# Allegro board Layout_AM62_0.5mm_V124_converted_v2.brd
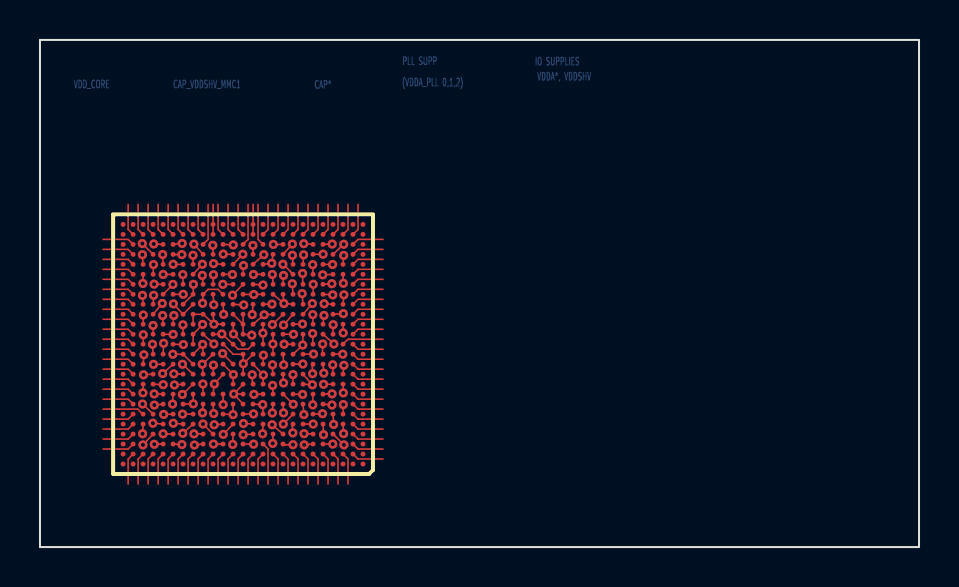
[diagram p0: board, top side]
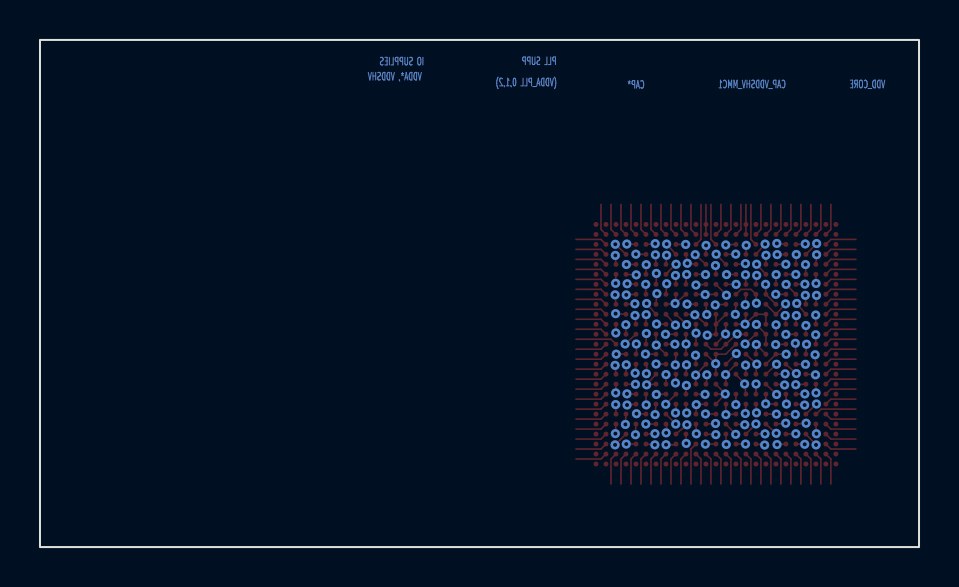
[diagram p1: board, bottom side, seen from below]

Outline 43.98 x 25.4 mm; copper layers: TOP, INNER LAYER 2, INNER LAYER 3, INNER LAYER 4, INNER LAYER 5, BOTTOM. Coordinates in mm from the lower left corner of the outline.
Outline path: rectangle 0,0 43.98,25.4

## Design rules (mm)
constraint set DEFAULT: min track width 0.081

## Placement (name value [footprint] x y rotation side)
U1  -  [AM62_20210511]  10.16 10.16 0 top

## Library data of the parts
U1 = AM62_20210511

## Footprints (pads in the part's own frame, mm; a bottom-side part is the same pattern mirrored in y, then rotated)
AM62_20210511
  round 0.249 smd: A1(6,-6) A2(5.5,-6) A3(5,-6) A4(4.5,-6) A5(4,-6) A6(3.5,-6) A7(3,-6) A8(2.5,-6) A9(2,-6) A10(1.5,-6) A11(1,-6) A12(0.5,-6) A13(0,-6) A14(-0.5,-6) A15(-1,-6) A16(-1.5,-6) A17(-2,-6) A18(-2.5,-6) A19(-3,-6) A20(-3.5,-6) A21(-4,-6) A22(-4.5,-6) A23(-5,-6) A24(-5.5,-6) A25(-6,-6) AA1(6,4) AA2(5.5,4) AA3(5,4) AA5(4,4) AA7(3,4) AA8(2.5,4) AA11(1,4) AA12(0.5,4) AA14(-0.5,4) AA15(-1,4) AA18(-2.5,4) AA19(-3,4) AA21(-4,4) AA23(-5,4) AA24(-5.5,4) AA25(-6,4) AB1(6,4.5) AB2(5.5,4.5) AB4(4.5,4.5) AB6(3.5,4.5) AB9(2,4.5) AB10(1.5,4.5) AB12(0.5,4.5) AB14(-0.5,4.5) AB16(-1.5,4.5) AB17(-2,4.5) AB20(-3.5,4.5) AB22(-4.5,4.5) AB24(-5.5,4.5) AB25(-6,4.5) AC1(6,5) AC2(5.5,5) AC5(4,5) AC6(3.5,5) AC9(2,5) AC11(1,5) AC13(0,5) AC15(-1,5) AC17(-2,5) AC20(-3.5,5) AC21(-4,5) AC24(-5.5,5) AC25(-6,5) AD1(6,5.5) AD2(5.5,5.5) AD3(5,5.5) AD4(4.5,5.5) AD5(4,5.5) AD6(3.5,5.5) AD7(3,5.5) AD8(2.5,5.5) AD9(2,5.5) AD10(1.5,5.5) AD11(1,5.5) AD12(0.5,5.5) AD13(0,5.5) AD14(-0.5,5.5) AD15(-1,5.5) AD16(-1.5,5.5) AD17(-2,5.5) AD18(-2.5,5.5) AD19(-3,5.5) AD20(-3.5,5.5) AD21(-4,5.5) AD22(-4.5,5.5) AD23(-5,5.5) AD24(-5.5,5.5) AD25(-6,5.5) AE1(6,6) AE2(5.5,6) AE3(5,6) AE4(4.5,6) AE5(4,6) AE6(3.5,6) AE7(3,6) AE8(2.5,6) AE9(2,6) AE10(1.5,6) AE11(1,6) AE12(0.5,6) AE13(0,6) AE14(-0.5,6) AE15(-1,6) AE16(-1.5,6) AE17(-2,6) AE18(-2.5,6) AE19(-3,6) AE20(-3.5,6) AE21(-4,6) AE22(-4.5,6) AE23(-5,6) AE24(-5.5,6) AE25(-6,6) B1(6,-5.5) B2(5.5,-5.5) B3(5,-5.5) B4(4.5,-5.5) B5(4,-5.5) B6(3.5,-5.5) B7(3,-5.5) B8(2.5,-5.5) B9(2,-5.5) B10(1.5,-5.5) B11(1,-5.5) B12(0.5,-5.5) B13(0,-5.5) B14(-0.5,-5.5) B15(-1,-5.5) B16(-1.5,-5.5) B17(-2,-5.5) B18(-2.5,-5.5) B19(-3,-5.5) B20(-3.5,-5.5) B21(-4,-5.5) B22(-4.5,-5.5) B23(-5,-5.5) B24(-5.5,-5.5) B25(-6,-5.5) C1(6,-5) C2(5.5,-5) C5(4,-5) C6(3.5,-5) C9(2,-5) C11(1,-5) C13(0,-5) C15(-1,-5) C17(-2,-5) C20(-3.5,-5) C21(-4,-5) C24(-5.5,-5) C25(-6,-5) D1(6,-4.5) D2(5.5,-4.5) D4(4.5,-4.5) D6(3.5,-4.5) D9(2,-4.5) D10(1.5,-4.5) D12(0.5,-4.5) D14(-0.5,-4.5) D16(-1.5,-4.5) D17(-2,-4.5) D20(-3.5,-4.5) D22(-4.5,-4.5) D24(-5.5,-4.5) D25(-6,-4.5) E1(6,-4) E2(5.5,-4) E3(5,-4) E5(4,-4) E7(3,-4) E8(2.5,-4) E11(1,-4) E12(0.5,-4) E14(-0.5,-4) E15(-1,-4) E18(-2.5,-4) E19(-3,-4) E21(-4,-4) E23(-5,-4) E24(-5.5,-4) E25(-6,-4) F1(6,-3.5) F2(5.5,-3.5) F3(5,-3.5) F4(4.5,-3.5) F6(3.5,-3.5) F8(2.5,-3.5) F11(1,-3.5) F13(0,-3.5) F15(-1,-3.5) F18(-2.5,-3.5) F20(-3.5,-3.5) F22(-4.5,-3.5) F23(-5,-3.5) F24(-5.5,-3.5) F25(-6,-3.5) G1(6,-3) G2(5.5,-3) G5(4,-3) G7(3,-3) G9(2,-3) G10(1.5,-3) G12(0.5,-3) G13(0,-3) G14(-0.5,-3) G16(-1.5,-3) G17(-2,-3) G19(-3,-3) G21(-4,-3) G24(-5.5,-3) G25(-6,-3) H1(6,-2.5) H2(5.5,-2.5) H5(4,-2.5) H6(3.5,-2.5) H8(2.5,-2.5) H9(2,-2.5) H10(1.5,-2.5) H11(1,-2.5) H13(0,-2.5) H15(-1,-2.5) H16(-1.5,-2.5) H17(-2,-2.5) H18(-2.5,-2.5) H20(-3.5,-2.5) H21(-4,-2.5) H24(-5.5,-2.5) H25(-6,-2.5) J1(6,-2) J2(5.5,-2) J3(5,-2) J4(4.5,-2) J7(3,-2) J8(2.5,-2) J11(1,-2) J12(0.5,-2) J13(0,-2) J14(-0.5,-2) J18(-2.5,-2) J19(-3,-2) J22(-4.5,-2) J23(-5,-2) J24(-5.5,-2) J25(-6,-2) K1(6,-1.5) K2(5.5,-1.5) K3(5,-1.5) K4(4.5,-1.5) K7(3,-1.5) K9(2,-1.5) K10(1.5,-1.5) K13(0,-1.5) K15(-1,-1.5) K16(-1.5,-1.5) K17(-2,-1.5) K18(-2.5,-1.5) K19(-3,-1.5) K22(-4.5,-1.5) K24(-5.5,-1.5) K25(-6,-1.5) L1(6,-1) L2(5.5,-1) L5(4,-1) L6(3.5,-1) L8(2.5,-1) L11(1,-1) L12(0.5,-1) L14(-0.5,-1) L15(-1,-1) L18(-2.5,-1) L20(-3.5,-1) L21(-4,-1) L23(-5,-1) L24(-5.5,-1) L25(-6,-1) M1(6,-0.5) M2(5.5,-0.5) M4(4.5,-0.5) M5(4,-0.5) M7(3,-0.5) M8(2.5,-0.5) M9(2,-0.5) M10(1.5,-0.5) M12(0.5,-0.5) M13(0,-0.5) M16(-1.5,-0.5) M17(-2,-0.5) M18(-2.5,-0.5) M19(-3,-0.5) M21(-4,-0.5) M22(-4.5,-0.5) M24(-5.5,-0.5) M25(-6,-0.5) N1(6,0) N2(5.5,0) N3(5,0) N6(3.5,0) N8(2.5,0) N11(1,0) N12(0.5,0) N13(0,0) N14(-0.5,0) N15(-1,0) N18(-2.5,0) N20(-3.5,0) N23(-5,0) N24(-5.5,0) N25(-6,0) P1(6,0.5) P2(5.5,0.5) P4(4.5,0.5) P5(4,0.5) P7(3,0.5) P9(2,0.5) P10(1.5,0.5) P13(0,0.5) P16(-1.5,0.5) P17(-2,0.5) P18(-2.5,0.5) P19(-3,0.5) P21(-4,0.5) P22(-4.5,0.5) P24(-5.5,0.5) P25(-6,0.5) R1(6,1) R2(5.5,1) R3(5,1) R5(4,1) R6(3.5,1) R8(2.5,1) R11(1,1) R12(0.5,1) R13(0,1) R14(-0.5,1) R15(-1,1) R18(-2.5,1) R20(-3.5,1) R21(-4,1) R23(-5,1) R24(-5.5,1) R25(-6,1) T1(6,1.5) T2(5.5,1.5) T4(4.5,1.5) T7(3,1.5) T8(2.5,1.5) T9(2,1.5) T10(1.5,1.5) T13(0,1.5) T14(-0.5,1.5) T16(-1.5,1.5) T17(-2,1.5) T18(-2.5,1.5) T19(-3,1.5) T22(-4.5,1.5) T24(-5.5,1.5) T25(-6,1.5) U1(6,2) U2(5.5,2) U3(5,2) U4(4.5,2) U7(3,2) U8(2.5,2) U11(1,2) U12(0.5,2) U14(-0.5,2) U15(-1,2) U18(-2.5,2) U19(-3,2) U22(-4.5,2) U23(-5,2) U24(-5.5,2) U25(-6,2) V1(6,2.5) V2(5.5,2.5) V5(4,2.5) V6(3.5,2.5) V8(2.5,2.5) V9(2,2.5) V10(1.5,2.5) V11(1,2.5) V13(0,2.5) V15(-1,2.5) V16(-1.5,2.5) V17(-2,2.5) V18(-2.5,2.5) V20(-3.5,2.5) V21(-4,2.5) V24(-5.5,2.5) V25(-6,2.5) W1(6,3) W2(5.5,3) W5(4,3) W7(3,3) W9(2,3) W10(1.5,3) W12(0.5,3) W13(0,3) W14(-0.5,3) W16(-1.5,3) W17(-2,3) W19(-3,3) W21(-4,3) W24(-5.5,3) W25(-6,3) Y1(6,3.5) Y2(5.5,3.5) Y3(5,3.5) Y4(4.5,3.5) Y6(3.5,3.5) Y8(2.5,3.5) Y11(1,3.5) Y13(0,3.5) Y15(-1,3.5) Y18(-2.5,3.5) Y20(-3.5,3.5) Y22(-4.5,3.5) Y23(-5,3.5) Y24(-5.5,3.5) Y25(-6,3.5)

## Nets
VDD_CANUART: U1.F8
VDD_CORE: U1.H8 U1.J11 U1.J14 U1.K17 U1.L12 U1.L15 U1.M16 U1.N8 U1.N11 U1.N13 U1.P17 U1.R11 U1.R14 U1.U12 U1.V8 U1.V15 U1.V17
VDDA_1P8_CSIRX: U1.W14
VDDA_1P8_OLDI-0: U1.W9
VDDA_1P8_OLDI-1: U1.W10
VDDA_1P8_USB: U1.Y11
VDDA_3P3_USB: U1.Y13
VDDA_CORE_CSIRX: U1.W13
VDDA_CORE_USB: U1.W12
VDDA_MCU: U1.L11
VDDA_PLL0: U1.U11
VDDA_PLL1: U1.U15
VDDA_PLL2: U1.L14
VDDA_TEMP0: U1.T9
VDDA_TEMP1: U1.G16
VDDR_CORE: U1.J12 U1.K16 U1.N12 U1.N14 U1.P16 U1.R12 U1.T10 U1.U14
VDDS_DDR-0: U1.K9
VDDS_DDR-1: U1.L8
VDDS_DDR-2: U1.P9
VDDS_DDR-3: U1.R8
VDDS_DDR_C: U1.M9
VDDS_OSC: U1.G7
VDDSHV0: U1.F15 U1.G14
VDDSHV1: U1.L18 U1.M19
VDDSHV2: U1.W16 U1.W19
VDDSHV3: U1.N18 U1.P18 U1.T19 U1.U18
VDDSHV4: U1.T7
VDDSHV5: U1.G17
VDDSHV6: U1.J18
VDDSHV_CANUART: U1.H9
VDDSHV_MCU: U1.F11 U1.G12
VSS: U1.A1 U1.A24 U1.A25 U1.AA11 U1.AB10 U1.AD1 U1.AD12 U1.AD16 U1.AD25 U1.AE1 U1.AE12 U1.AE16 U1.AE24 U1.AE25 U1.B25 U1.F13 U1.G13 U1.G19 U1.H13 U1.H16 U1.H18 U1.J7 U1.J13 U1.K7 U1.K13 U1.K15 U1.K19 U1.M7 U1.M8 U1.M10 U1.M12 U1.M13 U1.M17 U1.M18 U1.N15 U1.P7 U1.P10 U1.P13 U1.R13 U1.R15 U1.R18 U1.T8 U1.T13 U1.T14 U1.T16 U1.T17 U1.T18 U1.U8 U1.U19 U1.V9 U1.V10 U1.V11 U1.V13 U1.V16 U1.V18 U1.W7
ATEST0: U1.F6
ATEST1: U1.AE2
CAP_VDDS0: U1.H15
CAP_VDDS1: U1.K18
CAP_VDDS2: U1.W17
CAP_VDDS3: U1.P19
CAP_VDDS4: U1.U7
CAP_VDDS5: U1.H17
CAP_VDDS6: U1.J19
CAP_VDDS_CANUART: U1.G9
CAP_VDDS_MCU: U1.H11
CSI0_ATB_0_H: U1.AA12
CSI0_ATB_1_H: U1.Y15
CSI0_RXCLKN: U1.AD15
CSI0_RXCLKP: U1.AE15
CSI0_RXN0: U1.AB14
CSI0_RXN1: U1.AD14
CSI0_RXN2: U1.AD13
CSI0_RXN3: U1.AB12
CSI0_RXP0: U1.AC15
CSI0_RXP1: U1.AE14
CSI0_RXP2: U1.AE13
CSI0_RXP3: U1.AC13
CSI0_RXRCALIB: U1.AA14
DDR0_A0: U1.J1
DDR0_A1: U1.J2
DDR0_A2: U1.K3
DDR0_A3: U1.L5
DDR0_A4: U1.K4
DDR0_A5: U1.K1
DDR0_A6: U1.R2
DDR0_A7: U1.P2
DDR0_A8: U1.P1
DDR0_A9: U1.P4
DDR0_A10: U1.R5
DDR0_A11: U1.P5
DDR0_A12: U1.R6
DDR0_A13: U1.R1
DDR0_ACT_N: U1.N6
DDR0_ALERT_N: U1.R3
DDR0_ATB0: U1.T2
DDR0_ATB1: U1.U4
DDR0_BA0: U1.M1
DDR0_BA1: U1.N1
DDR0_BG0: U1.T4
DDR0_BG1: U1.N2
DDR0_CAL0: U1.M2
DDR0_CAS_N: U1.M4
DDR0_CK0: U1.L1
DDR0_CK0_N: U1.L2
DDR0_CKE0: U1.H2
DDR0_CKE1: U1.J4
DDR0_CS0_N: U1.L6
DDR0_CS1_N: U1.K2
DDR0_DM0: U1.H5
DDR0_DM1: U1.W5
DDR0_DQ0: U1.F4
DDR0_DQ1: U1.G5
DDR0_DQ2: U1.F3
DDR0_DQ3: U1.H6
DDR0_DQ4: U1.E3
DDR0_DQ5: U1.G2
DDR0_DQ6: U1.F2
DDR0_DQ7: U1.F1
DDR0_DQ8: U1.U1
DDR0_DQ9: U1.U3
DDR0_DQ10: U1.U2
DDR0_DQ11: U1.V5
DDR0_DQ12: U1.W2
DDR0_DQ13: U1.V6
DDR0_DQ14: U1.Y1
DDR0_DQ15: U1.W1
DDR0_DQS0: U1.E1
DDR0_DQS0_N: U1.E2
DDR0_DQS1: U1.V1
DDR0_DQS1_N: U1.V2
DDR0_ODT0: U1.H1
DDR0_ODT1: U1.J3
DDR0_PAR: U1.T1
DDR0_RAS_N: U1.M5
DDR0_RESET0_N: U1.G1
DDR0_WE_N: U1.N3
EMU0: U1.E12
EMU1: U1.A10
EXT_REFCLK1: U1.D16
EXTINTN: U1.A18
GPMC0_AD0: U1.M25
GPMC0_AD1: U1.N23
GPMC0_AD2: U1.N24
GPMC0_AD3: U1.N25
GPMC0_AD4: U1.P24
GPMC0_AD5: U1.P22
GPMC0_AD6: U1.P21
GPMC0_AD7: U1.R24
GPMC0_AD8: U1.R25
GPMC0_AD9: U1.T25
GPMC0_AD10: U1.T24
GPMC0_AD11: U1.R21
GPMC0_AD12: U1.R20
GPMC0_AD13: U1.T22
GPMC0_AD14: U1.U25
GPMC0_AD15: U1.U24
GPMC0_ADVN_ALE: U1.L23
GPMC0_BE0N_CLE: U1.N20
GPMC0_BE1N: U1.M24
GPMC0_CLK: U1.R23
GPMC0_CLKLB: U1.P25
GPMC0_CSN0: U1.M21
GPMC0_CSN1: U1.L20
GPMC0_CSN2: U1.L21
GPMC0_CSN3: U1.K22
GPMC0_DIR: U1.M22
GPMC0_OEN_REN: U1.L24
GPMC0_WAIT0: U1.U23
GPMC0_WAIT1: U1.V25
GPMC0_WEN: U1.L25
GPMC0_WPN: U1.K25
I2C0_SCL: U1.B16
I2C0_SDA: U1.A16
I2C1_SCL: U1.B17
I2C1_SDA: U1.A17
IFORCE: U1.B1
MCAN0_RX: U1.E15
MCAN0_TX: U1.C15
MCASP0_ACLKR: U1.D20
MCASP0_ACLKX: U1.B20
MCASP0_AFSR: U1.E19
MCASP0_AFSX: U1.A20
MCASP0_AXR0: U1.E18
MCASP0_AXR1: U1.B18
MCASP0_AXR2: U1.A19
MCASP0_AXR3: U1.B19
MCU_ERRORN: U1.C2
MCU_I2C0_SCL: U1.A8
MCU_I2C0_SDA: U1.D10
MCU_MCAN0_RX: U1.B3
MCU_MCAN0_TX: U1.D6
MCU_MCAN1_RX: U1.D4
MCU_MCAN1_TX: U1.E5
MCU_OSC0_XI: U1.B2
MCU_OSC0_XO: U1.A3
MCU_PORZ: U1.D2
MCU_RESETSTATZ: U1.B12
MCU_RESETZ: U1.E11
MCU_SPI0_CLK: U1.E8
MCU_SPI0_CS0: U1.A7
MCU_SPI0_CS1: U1.B8
MCU_SPI0_D0: U1.D9
MCU_SPI0_D1: U1.C9
MCU_UART0_CTSN: U1.A6
MCU_UART0_RTSN: U1.B6
MCU_UART0_RXD: U1.B5
MCU_UART0_TXD: U1.A5
MDIO0_MDC: U1.AD24
MDIO0_MDIO: U1.AB22
MMC0_CLK: U1.Y4
MMC0_CLKLB: U1.AA3
MMC0_CMD: U1.Y3
MMC0_DAT0: U1.AA1
MMC0_DAT1: U1.Y2
MMC0_DAT2: U1.AA2
MMC0_DAT3: U1.AB1
MMC0_DAT4: U1.AB2
MMC0_DAT5: U1.AC1
MMC0_DAT6: U1.AD2
MMC0_DAT7: U1.AC2
MMC1_CLK: U1.B22
MMC1_CLKLB: U1.C21
MMC1_CMD: U1.A21
MMC1_DAT0: U1.A22
MMC1_DAT1: U1.B21
MMC1_DAT2: U1.D22
MMC1_DAT3: U1.E23
MMC1_SDCD: U1.D17
MMC1_SDWP: U1.C17
MMC2_CLK: U1.D25
MMC2_CLKLB: U1.D24
MMC2_CMD: U1.C24
MMC2_DAT0: U1.B24
MMC2_DAT1: U1.C25
MMC2_DAT2: U1.E24
MMC2_DAT3: U1.E25
MMC2_SDCD: U1.A23
MMC2_SDWP: U1.B23
OLDI0_A0N: U1.AA5
OLDI0_A0P: U1.Y6
OLDI0_A1N: U1.AD3
OLDI0_A1P: U1.AB4
OLDI0_A2N: U1.Y8
OLDI0_A2P: U1.AA8
OLDI0_A3N: U1.AB6
OLDI0_A3P: U1.AA7
OLDI0_A4N: U1.AC6
OLDI0_A4P: U1.AC5
OLDI0_A5N: U1.AE5
OLDI0_A5P: U1.AD6
OLDI0_A6N: U1.AE6
OLDI0_A6P: U1.AD7
OLDI0_A7N: U1.AD8
OLDI0_A7P: U1.AE7
OLDI0_CLK0N: U1.AD4
OLDI0_CLK0P: U1.AE3
OLDI0_CLK1N: U1.AE4
OLDI0_CLK1P: U1.AD5
OSPI0_CLK: U1.H24
OSPI0_CSN0: U1.F24
OSPI0_CSN1: U1.H20
OSPI0_CSN2: U1.G21
OSPI0_CSN3: U1.H21
OSPI0_D0: U1.F23
OSPI0_D1: U1.G25
OSPI0_D2: U1.G24
OSPI0_D3: U1.F25
OSPI0_D4: U1.J23
OSPI0_D5: U1.J25
OSPI0_D6: U1.H25
OSPI0_D7: U1.K24
OSPI0_DQS: U1.J24
OSPI0_LBCLKO: U1.J22
PMIC_LPM_EN0: U1.B7
PORZ_OUT: U1.E21
RESET_REQZ: U1.F20
RESETSTATZ: U1.F22
RGMII1_RD0: U1.AB17
RGMII1_RD1: U1.AC17
RGMII1_RD2: U1.AB16
RGMII1_RD3: U1.AA15
RGMII1_RX_CTL: U1.AE17
RGMII1_RXC: U1.AD17
RGMII1_TD0: U1.AE20
RGMII1_TD1: U1.AD20
RGMII1_TD2: U1.AE18
RGMII1_TD3: U1.AD18
RGMII1_TX_CTL: U1.AD19
RGMII1_TXC: U1.AE19
RGMII2_RD0: U1.AE23
RGMII2_RD1: U1.AB20
RGMII2_RD2: U1.AC21
RGMII2_RD3: U1.AE22
RGMII2_RX_CTL: U1.AD22
RGMII2_RXC: U1.AD23
RGMII2_TD0: U1.Y18
RGMII2_TD1: U1.AA18
RGMII2_TD2: U1.AD21
RGMII2_TD3: U1.AC20
RGMII2_TX_CTL: U1.AA19
RGMII2_TXC: U1.AE21
SPI0_CLK: U1.A14
SPI0_CS0: U1.A13
SPI0_CS1: U1.C13
SPI0_D0: U1.B13
SPI0_D1: U1.B14
TCK: U1.C11
TDI: U1.A11
TDO: U1.D12
TEMP_DIODE_P: U1.E7
TMS: U1.B11
TRSTN: U1.B10
UART0_CTSN: U1.A15
UART0_RTSN: U1.B15
UART0_RXD: U1.D14
UART0_TXD: U1.E14
USB0_DM: U1.AE11
USB0_DP: U1.AD11
USB0_DRVVBUS: U1.C20
USB0_ID: U1.AE10
USB0_RCALIB: U1.AD10
USB0_VBUS: U1.AC11
USB1_DM: U1.AD9
USB1_DP: U1.AE9
USB1_DRVVBUS: U1.F18
USB1_ID: U1.AC9
USB1_RCALIB: U1.AB9
USB1_VBUS: U1.AE8
VMON_1P8_SOC: U1.G10
VMON_3P3_SOC: U1.K10
VMON_VSYS: U1.H10
VOUT0_DATA0: U1.U22
VOUT0_DATA1: U1.V24
VOUT0_DATA2: U1.W25
VOUT0_DATA3: U1.W24
VOUT0_DATA4: U1.Y25
VOUT0_DATA5: U1.Y24
VOUT0_DATA6: U1.Y23
VOUT0_DATA7: U1.AA25
VOUT0_DATA8: U1.V21
VOUT0_DATA9: U1.W21
VOUT0_DATA10: U1.V20
VOUT0_DATA11: U1.AA23
VOUT0_DATA12: U1.AB25
VOUT0_DATA13: U1.AA24
VOUT0_DATA14: U1.Y22
VOUT0_DATA15: U1.AB24
VOUT0_DE: U1.AA21
VOUT0_HSYNC: U1.AC25
VOUT0_PCLK: U1.Y20
VOUT0_VSYNC: U1.AC24
VPP: U1.J8
VSENSE: U1.A2
WKUP_CLKOUT0: U1.A12
WKUP_I2C0_SCL: U1.B9
WKUP_I2C0_SDA: U1.A9
WKUP_LFOSC0_XI: U1.C1
WKUP_LFOSC0_XO: U1.D1
WKUP_UART0_CTSN: U1.C6
WKUP_UART0_RTSN: U1.A4
WKUP_UART0_RXD: U1.B4
WKUP_UART0_TXD: U1.C5

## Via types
v1: diameter 0.457, hole 0.203, TOP to BOTTOM, 198 vias

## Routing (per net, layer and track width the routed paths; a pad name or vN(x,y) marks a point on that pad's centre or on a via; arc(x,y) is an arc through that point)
VDD_CANUART: length 0.7
  TOP w0.081: v1(12.17,6.16) U1.F8
VDD_CORE: length 10.2
  TOP w0.081: U1.M16 v1(8.12,9.16) U1.K17 ; U1.P17 v1(8.7,10.17) ; U1.R11 v1(11.16,10.71) U1.N11 ; v1(8.14,12.21) U1.V17 8.41,12.91 8.91,12.91 9.16,12.66 U1.V15 ; U1.J11 v1(11.17,8.61) U1.L12 ; U1.R14 v1(9.68,10.67) U1.N13 ; U1.L15 v1(9.68,8.64) U1.J14 ; v1(12.21,10.16) U1.N8 ; U1.H8 v1(13.14,7.64) ; v1(12.62,13.19) U1.V8 ; v1(10.62,11.65) U1.U12
VDDA_1P8_CSIRX: length 0.5
  TOP w0.081: v1(9.15,13.16) U1.W14
VDDA_1P8_OLDI-0: length 0.4
  TOP w0.081: U1.W9 v1(12.18,13.6)
VDDA_1P8_OLDI-1: length 0.5
  TOP w0.081: U1.W10 11.66,13.28 v1(11.62,13.65)
VDDA_1P8_USB: length 0.5
  TOP w0.081: v1(10.68,13.65) 10.69,13.66 U1.Y11
VDDA_3P3_USB: length 0.4
  TOP w0.081: U1.Y13 v1(10.18,14.1)
VDDA_CORE_CSIRX: length 0.8
  TOP w0.081: v1(9.63,12.61) U1.W13
VDDA_CORE_USB: length 0.5
  TOP w0.081: U1.W12 v1(11.16,13.13)
VDDA_MCU: length 0.5
  TOP w0.081: U1.L11 v1(11.18,9.61)
VDDA_PLL0: length 0.4
  TOP w0.081: U1.U11 v1(11.61,12.17)
VDDA_PLL1: length 0.5
  TOP w0.081: U1.U15 v1(9.19,11.66)
VDDA_PLL2: length 0.7
  TOP w0.081: v1(9.14,9.69) U1.L14
VDDA_TEMP0: length 0.7
  TOP w0.081: v1(11.63,11.15) U1.T9
VDDA_TEMP1: length 0.5
  TOP w0.081: U1.G16 v1(8.69,6.69)
VDDR_CORE: length 5.1
  TOP w0.081: U1.R12 v1(11.21,11.63) U1.T10 ; U1.P16 9.1,10.64 v1(9.1,10.67) 9.15,10.64 U1.N14 9.91,9.91 10.41,9.91 U1.N12 ; U1.U14 v1(10.19,12.13) ; U1.J12 10.63,8.28 v1(10.62,8.63) ; U1.K16 v1(8.68,9.11)
VDDS_DDR-0: length 0.4
  TOP w0.081: U1.K9 v1(12.19,8.22)
VDDS_DDR-1: length 0.5
  TOP w0.081: U1.L8 v1(13.15,9.17)
VDDS_DDR-2: length 0.5
  TOP w0.081: U1.P9 v1(12.68,10.66)
VDDS_DDR-3: length 0.5
  TOP w0.081: U1.R8 v1(13.13,11.17)
VDDS_DDR_C: length 0.5
  TOP w0.081: U1.M9 v1(12.19,9.12)
VDDS_OSC: length 0.5
  TOP w0.081: U1.G7 v1(13.2,6.63)
VDDSHV0: length 1
  TOP w0.081: U1.G14 v1(9.66,6.63) U1.F15
VDDSHV1: length 1.2
  TOP w0.081: U1.L18 U1.M19 v1(6.65,9.66)
VDDSHV2: length 1
  TOP w0.081: v1(7.15,13.65) U1.W19 ; U1.W16 v1(8.68,13.64)
VDDSHV3: length 2.6
  TOP w0.081: v1(6.68,12.18) U1.T19 U1.U18 ; v1(8.14,11.15) U1.P18 U1.N18
VDDSHV4: length 0.7
  TOP w0.081: U1.T7 v1(13.63,12.2)
VDDSHV5: length 0.4
  TOP w0.081: v1(8.13,6.72) U1.G17
VDDSHV6: length 0.7
  TOP w0.081: v1(7.12,7.64) U1.J18
VDDSHV_CANUART: length 0.7
  TOP w0.081: U1.H9 v1(12.67,7.15)
VDDSHV_MCU: length 1
  TOP w0.081: U1.G12 v1(11.14,7.13) U1.F11
VSS: length 27.3
  TOP w0.081: v1(10.17,9.18) U1.M13 9.67,9.66 9.16,10.16 U1.N15 ; v1(10.17,9.18) U1.K13 ; v1(10.17,9.18) U1.M12 ; U1.K7 v1(13.63,8.13) U1.J7 ; U1.AA11 v1(11.59,14.21) U1.AB10 ; U1.U19 7.16,12.16 7.66,12.66 U1.V18 v1(7.68,13.16) ; U1.P10 v1(11.65,10.17) U1.M10 ; U1.T14 U1.R13 ; U1.R13 U1.T13 ; U1.R13 U1.P13 v1(10.6,10.61) ; U1.W7 13.15,13.16 v1(13.14,13.71) ; U1.H18 v1(7.67,7.17) U1.G19 ; U1.K15 v1(8.72,8.17) U1.H16 ; U1.M8 v1(13.15,10.12) U1.P7 ; U1.V9 v1(12.2,12.2) ; v1(12.2,12.2) U1.V10 ; v1(12.2,12.2) U1.U8 ; v1(8.7,11.16) U1.R15 ; v1(8.7,11.16) U1.T16 ; v1(8.7,11.16) U1.T17 U1.T18 U1.R18 ; U1.AD12 U1.AE12 10.66,17.16 ; U1.M18 v1(8.14,10.15) U1.M17 ; U1.H13 v1(9.69,7.67) ; v1(9.69,7.67) U1.J13 ; v1(9.69,7.67) U1.G13 ; U1.M7 v1(13.69,9.67) ; U1.F13 v1(10.68,6.67) ; U1.V11 v1(10.7,12.65) U1.V13 ; v1(12.18,11.12) U1.T8 ; U1.V16 v1(8.69,12.14) ; v1(6.7,8.68) U1.K19 ; 8.66,17.16 U1.AE16 U1.AD16
ATEST0: length 0.5
  TOP w0.081: U1.F6 v1(14.14,6.68)
CAP_VDDS0: length 0.5
  TOP w0.081: U1.H15 v1(9.16,7.14)
CAP_VDDS1: length 0.7
  TOP w0.081: v1(7.13,9.16) U1.K18
CAP_VDDS2: length 0.4
  TOP w0.081: v1(8.12,13.61) U1.W17
CAP_VDDS3: length 0.5
  TOP w0.081: v1(7.15,11.13) U1.P19
CAP_VDDS4: length 0.5
  TOP w0.081: v1(13.11,12.69) U1.U7
CAP_VDDS5: length 0.5
  TOP w0.081: v1(8.15,8.17) U1.H17
CAP_VDDS6: length 0.4
  TOP w0.081: v1(6.72,8.12) U1.J19
CAP_VDDS_CANUART: length 0.4
  TOP w0.081: U1.G9 v1(12.18,6.72)
CAP_VDDS_MCU: length 0.5
  TOP w0.081: v1(10.7,7.65) U1.H11
CSI0_ATB_0_H: length 0.7
  TOP w0.081: U1.AA12 v1(11.2,14.64)
CSI0_ATB_1_H: length 0.5
  TOP w0.081: U1.Y15 v1(9.63,13.65)
CSI0_RXCLKN: length 1.6
  TOP w0.081: 8.91,17.16 8.91,15.91 U1.AD15
CSI0_RXN0: length 0.5
  TOP w0.081: v1(9.17,14.67) U1.AB14
CSI0_RXN1: length 1.6
  TOP w0.081: U1.AD14 9.41,15.91 9.41,17.16
CSI0_RXN2: length 1.6
  TOP w0.081: U1.AD13 9.91,15.91 9.91,17.16
CSI0_RXN3: length 0.4
  TOP w0.081: v1(10.65,15.11) U1.AB12
CSI0_RXP0: length 0.5
  TOP w0.081: U1.AC15 v1(9.67,15.13)
CSI0_RXP3: length 2.1
  TOP w0.081: 10.41,17.16 10.41,15.41 U1.AC13
CSI0_RXRCALIB: length 0.7
  TOP w0.081: U1.AA14 v1(10.15,14.67)
DDR0_A1: length 1.6
  TOP w0.081: 17.16,7.91 15.91,7.91 U1.J2
DDR0_A2: length 0.4
  TOP w0.081: U1.K3 v1(15.2,9.1)
DDR0_A3: length 0.5
  TOP w0.081: U1.L5 v1(14.2,8.71)
DDR0_A4: length 0.5
  TOP w0.081: v1(14.65,9.13) U1.K4
DDR0_A6: length 1.6
  TOP w0.081: 17.16,11.41 15.91,11.41 U1.R2
DDR0_A7: length 1.6
  TOP w0.081: 17.16,10.91 15.91,10.91 U1.P2
DDR0_A9: length 0.5
  TOP w0.081: U1.P4 v1(14.67,11.14)
DDR0_A10: length 0.4
  TOP w0.081: U1.R5 v1(14.21,11.6)
DDR0_A11: length 0.7
  TOP w0.081: U1.P5 v1(14.7,10.17)
DDR0_A12: length 0.5
  TOP w0.081: v1(13.65,11.64) U1.R6
DDR0_ACT_N: length 0.5
  TOP w0.081: v1(13.64,10.7) U1.N6
DDR0_ALERT_N: length 0.4
  TOP w0.081: U1.R3 v1(15.17,10.72)
DDR0_ATB0: length 1.6
  TOP w0.081: U1.T2 15.91,11.91 17.16,11.91
DDR0_ATB1: length 0.4
  TOP w0.081: v1(14.21,12.19) U1.U4
DDR0_BG0: length 0.5
  TOP w0.081: U1.T4 v1(15.18,11.69)
DDR0_BG1: length 1.6
  TOP w0.081: U1.N2 15.91,9.91 17.16,9.91
DDR0_CAL0: length 1.6
  TOP w0.081: 17.16,9.41 15.91,9.41 U1.M2
DDR0_CAS_N: length 0.5
  TOP w0.081: U1.M4 14.66,9.67 v1(15.15,9.66)
DDR0_CK0_N: length 1.6
  TOP w0.081: U1.L2 15.91,8.91 17.16,8.91
DDR0_CKE0: length 1.6
  TOP w0.081: 17.16,7.41 15.91,7.41 U1.H2
DDR0_CKE1: length 0.5
  TOP w0.081: v1(14.19,8.15) U1.J4
DDR0_CS0_N: length 0.5
  TOP w0.081: U1.L6 13.61,9.16 v1(13.64,8.69)
DDR0_CS1_N: length 1.6
  TOP w0.081: U1.K2 15.91,8.41 17.16,8.41
DDR0_DM0: length 0.5
  TOP w0.081: U1.H5 v1(14.61,7.67)
DDR0_DM1: length 0.4
  TOP w0.081: U1.W5 v1(14.6,13.19)
DDR0_DQ0: length 0.5
  TOP w0.081: U1.F4 v1(14.69,6.14)
DDR0_DQ1: length 0.4
  TOP w0.081: U1.G5 v1(14.61,7.12)
DDR0_DQ2: length 0.5
  TOP w0.081: U1.F3 v1(15.17,7.14)
DDR0_DQ3: length 0.5
  TOP w0.081: v1(13.65,7.12) U1.H6
DDR0_DQ4: length 0.5
  TOP w0.081: U1.E3 v1(15.19,5.68)
DDR0_DQ5: length 1.6
  TOP w0.081: U1.G2 15.91,6.91 17.16,6.91
DDR0_DQ6: length 1.6
  TOP w0.081: 17.16,6.41 15.91,6.41 U1.F2
DDR0_DQ9: length 0.5
  TOP w0.081: U1.U3 v1(15.2,12.63)
DDR0_DQ10: length 1.6
  TOP w0.081: U1.U2 15.91,12.41 17.16,12.41
DDR0_DQ11: length 0.5
  TOP w0.081: U1.V5 v1(14.65,12.63)
DDR0_DQ12: length 1.6
  TOP w0.081: U1.W2 15.91,13.41 17.16,13.41
DDR0_DQ13: length 0.5
  TOP w0.081: U1.V6 v1(13.67,13.16)
DDR0_DQS0_N: length 1.6
  TOP w0.081: U1.E2 15.91,5.91 17.16,5.91
DDR0_DQS1_N: length 1.6
  TOP w0.081: 17.16,12.91 15.91,12.91 U1.V2
DDR0_ODT1: length 0.4
  TOP w0.081: U1.J3 v1(15.17,7.72)
DDR0_RAS_N: length 0.5
  TOP w0.081: U1.M5 14.13,9.66 v1(14.14,10.17)
DDR0_WE_N: length 2.1
  TOP w0.081: U1.N3 15.41,10.41 17.16,10.41
EMU0: length 0.5
  TOP w0.081: v1(10.18,6.19) U1.E12
EXT_REFCLK1: length 0.7
  TOP w0.081: v1(8.16,6.16) U1.D16
GPMC0_AD1: length 0.5
  TOP w0.081: U1.N23 v1(5.17,10.63)
GPMC0_AD2: length 1.6
  TOP w0.081: U1.N24 4.41,10.41 3.16,10.41
GPMC0_AD4: length 1.6
  TOP w0.081: U1.P24 4.41,10.91 3.16,10.91
GPMC0_AD5: length 0.4
  TOP w0.081: v1(5.66,11.1) U1.P22
GPMC0_AD6: length 0.5
  TOP w0.081: U1.P21 v1(6.66,10.65)
GPMC0_AD7: length 1.6
  TOP w0.081: 3.16,11.41 4.41,11.41 U1.R24
GPMC0_AD10: length 1.6
  TOP w0.081: U1.T24 4.41,11.91 3.16,11.91
GPMC0_AD11: length 0.4
  TOP w0.081: v1(6.14,11.6) U1.R21
GPMC0_AD12: length 0.4
  TOP w0.081: U1.R20 v1(6.7,11.6)
GPMC0_AD13: length 0.7
  TOP w0.081: U1.T22 v1(6.12,12.2)
GPMC0_AD15: length 1.6
  TOP w0.081: U1.U24 4.41,12.41 3.16,12.41
GPMC0_ADVN_ALE: length 0.5
  TOP w0.081: U1.L23 v1(5.2,9.63)
GPMC0_BE0N_CLE: length 0.5
  TOP w0.081: U1.N20 v1(7.17,10.14)
GPMC0_BE1N: length 1.6
  TOP w0.081: U1.M24 4.41,9.91 3.16,9.91
GPMC0_CLK: length 0.5
  TOP w0.081: U1.R23 v1(5.17,11.62)
GPMC0_CSN0: length 0.5
  TOP w0.081: U1.M21 v1(6.19,10.21)
GPMC0_CSN1: length 0.7
  TOP w0.081: v1(6.14,8.69) U1.L20
GPMC0_CSN2: length 0.5
  TOP w0.081: v1(5.68,9.15) U1.L21
GPMC0_CSN3: length 0.5
  TOP w0.081: v1(5.18,8.63) U1.K22
GPMC0_DIR: length 0.5
  TOP w0.081: v1(5.63,10.16) U1.M22
GPMC0_OEN_REN: length 1.6
  TOP w0.081: 3.16,9.41 4.41,9.41 U1.L24
GPMC0_WAIT0: length 0.4
  TOP w0.081: v1(5.13,12.61) U1.U23
I2C0_SCL: length 1.6
  TOP w0.081: 8.41,3.16 8.41,4.41 U1.B16
I2C1_SCL: length 1.6
  TOP w0.081: U1.B17 7.91,4.41 7.91,3.16
MCAN0_RX: length 0.4
  TOP w0.081: v1(8.72,6.13) U1.E15
MCAN0_TX: length 0.5
  TOP w0.081: v1(8.68,5.16) U1.C15
MCASP0_ACLKR: length 0.5
  TOP w0.081: v1(6.16,5.67) U1.D20
MCASP0_ACLKX: length 1.6
  TOP w0.081: U1.B20 6.41,4.41 6.41,3.16
MCASP0_AFSR: length 0.5
  TOP w0.081: v1(6.67,6.2) 7.16,6.16 U1.E19
MCASP0_AXR0: length 0.7
  TOP w0.081: v1(7.14,5.7) U1.E18
MCASP0_AXR1: length 1.6
  TOP w0.081: 7.41,3.16 7.41,4.41 U1.B18
MCASP0_AXR3: length 1.6
  TOP w0.081: U1.B19 6.91,4.41 6.91,3.16
MCU_ERRORN: length 1.6
  TOP w0.081: 17.16,4.91 15.91,4.91 U1.C2
MCU_I2C0_SDA: length 0.5
  TOP w0.081: v1(11.65,5.19) U1.D10
MCU_MCAN0_RX: length 1.6
  TOP w0.081: 15.41,3.16 15.41,4.41 U1.B3
MCU_MCAN0_TX: length 0.5
  TOP w0.081: v1(13.21,5.68) U1.D6
MCU_MCAN1_RX: length 0.8
  TOP w0.081: U1.D4 v1(15.21,5.12)
MCU_MCAN1_TX: length 0.5
  TOP w0.081: U1.E5 v1(14.19,5.63)
MCU_OSC0_XI: length 1.6
  TOP w0.081: U1.B2 15.91,4.41 17.16,4.41
MCU_PORZ: length 1.6
  TOP w0.081: U1.D2 15.91,5.41 17.16,5.41
MCU_RESETSTATZ: length 1.6
  TOP w0.081: U1.B12 10.41,4.41 10.41,3.16
MCU_RESETZ: length 0.5
  TOP w0.081: v1(11.14,5.67) U1.E11
MCU_SPI0_CLK: length 0.5
  TOP w0.081: U1.E8 12.61,6.16 v1(12.65,5.72)
MCU_SPI0_CS1: length 1.6
  TOP w0.081: U1.B8 12.91,4.41 12.91,3.16
MCU_SPI0_D0: length 0.7
  TOP w0.081: v1(11.61,6.13) U1.D9
MCU_SPI0_D1: length 0.5
  TOP w0.081: v1(12.66,5.13) 12.28,5.12 U1.C9
MCU_UART0_RTSN: length 1.6
  TOP w0.081: U1.B6 13.91,4.41 13.91,3.16
MCU_UART0_RXD: length 1.6
  TOP w0.081: 14.41,3.16 14.41,4.41 U1.B5
MDIO0_MDC: length 1.6
  TOP w0.081: U1.AD24 4.41,15.91 4.41,17.16
MDIO0_MDIO: length 0.8
  TOP w0.081: v1(5.12,15.2) U1.AB22
MMC0_CLK: length 0.5
  TOP w0.081: v1(14.15,13.63) U1.Y4
MMC0_CLKLB: length 0.4
  TOP w0.081: U1.AA3 v1(15.19,14.61)
MMC0_CMD: length 0.4
  TOP w0.081: U1.Y3 v1(15.18,13.21)
MMC0_DAT1: length 1.6
  TOP w0.081: U1.Y2 15.91,13.91 17.16,13.91
MMC0_DAT2: length 1.6
  TOP w0.081: 17.16,14.41 15.91,14.41 U1.AA2
MMC0_DAT4: length 1.6
  TOP w0.081: 17.16,14.91 15.91,14.91 U1.AB2
MMC0_DAT6: length 1.6
  TOP w0.081: 15.91,17.16 15.91,15.91 U1.AD2
MMC0_DAT7: length 1.6
  TOP w0.081: 17.16,15.41 15.91,15.41 U1.AC2
MMC1_CLK: length 1.6
  TOP w0.081: U1.B22 5.41,4.41 5.41,3.16
MMC1_CLKLB: length 0.4
  TOP w0.081: v1(5.72,5.15) U1.C21
MMC1_DAT1: length 1.6
  TOP w0.081: 5.91,3.16 5.91,4.41 U1.B21
MMC1_DAT2: length 0.7
  TOP w0.081: v1(5.15,5.12) U1.D22
MMC1_DAT3: length 0.5
  TOP w0.081: v1(5.13,5.68) U1.E23
MMC1_SDCD: length 0.5
  TOP w0.081: v1(7.7,5.67) 7.71,5.69 U1.D17
MMC1_SDWP: length 0.4
  TOP w0.081: v1(7.72,5.11) U1.C17
MMC2_CLKLB: length 1.6
  TOP w0.081: U1.D24 4.41,5.41 3.16,5.41
MMC2_CMD: length 1.6
  TOP w0.081: 3.16,4.91 4.41,4.91 U1.C24
MMC2_DAT0: length 1.6
  TOP w0.081: U1.B24 4.41,4.41 4.41,3.16
MMC2_DAT2: length 1.6
  TOP w0.081: U1.E24 4.41,5.91 3.16,5.91
MMC2_SDWP: length 1.6
  TOP w0.081: 4.91,3.16 4.91,4.41 U1.B23
OLDI0_A0N: length 0.5
  TOP w0.081: U1.AA5 v1(14.64,14.15)
OLDI0_A0P: length 0.5
  TOP w0.081: v1(13.65,14.14) U1.Y6
OLDI0_A1N: length 1.6
  TOP w0.081: U1.AD3 15.41,15.91 15.41,17.16
OLDI0_A1P: length 0.7
  TOP w0.081: U1.AB4 v1(15.19,15.17)
OLDI0_A2N: length 0.7
  TOP w0.081: U1.Y8 12.53,13.79 12.53,13.8 12.33,14.01 12.31,14.01 v1(12.15,14.16)
OLDI0_A2P: length 0.5
  TOP w0.081: v1(12.63,14.62) U1.AA8
OLDI0_A3N: length 0.5
  TOP w0.081: U1.AB6 v1(14.17,14.67)
OLDI0_A3P: length 0.5
  TOP w0.081: U1.AA7 v1(13.19,14.64)
OLDI0_A4N: length 0.5
  TOP w0.081: v1(13.2,15.2) U1.AC6
OLDI0_A4P: length 0.5
  TOP w0.081: U1.AC5 v1(14.62,15.18)
OLDI0_A5P: length 1.6
  TOP w0.081: 13.91,17.16 13.91,15.91 U1.AD6
OLDI0_A6P: length 1.6
  TOP w0.081: 13.41,17.16 13.41,15.91 U1.AD7
OLDI0_A7N: length 1.6
  TOP w0.081: U1.AD8 12.91,15.91 12.91,17.16
OLDI0_CLK0N: length 1.6
  TOP w0.081: 14.91,17.16 14.91,15.91 U1.AD4
OLDI0_CLK1P: length 1.6
  TOP w0.081: 14.41,17.16 14.41,15.91 U1.AD5
OSPI0_CLK: length 1.6
  TOP w0.081: 3.16,7.91 4.41,7.91 U1.H24
OSPI0_CSN0: length 1.6
  TOP w0.081: U1.F24 4.41,6.41 3.16,6.41
OSPI0_CSN1: length 0.5
  TOP w0.081: v1(6.63,7.16) U1.H20
OSPI0_CSN2: length 0.4
  TOP w0.081: v1(5.72,7.11) U1.G21
OSPI0_CSN3: length 0.4
  TOP w0.081: v1(5.71,7.67) U1.H21
OSPI0_D0: length 2.1
  TOP w0.081: 3.16,6.91 4.89,6.91 5.15,6.65 U1.F23
OSPI0_D2: length 1.6
  TOP w0.081: U1.G24 4.41,7.41 3.16,7.41
OSPI0_D4: length 0.4
  TOP w0.081: v1(5.15,7.72) U1.J23
OSPI0_D7: length 1.6
  TOP w0.081: 3.16,8.91 4.41,8.91 U1.K24
OSPI0_DQS: length 1.6
  TOP w0.081: U1.J24 4.41,8.41 3.16,8.41
OSPI0_LBCLKO: length 0.5
  TOP w0.081: U1.J22 v1(6.17,8.13)
PMIC_LPM_EN0: length 1.6
  TOP w0.081: U1.B7 13.41,4.41 13.41,3.16
PORZ_OUT: length 0.5
  TOP w0.081: v1(5.65,6.2) U1.E21
RESET_REQZ: length 0.5
  TOP w0.081: v1(6.19,6.64) U1.F20
RESETSTATZ: length 0.7
  TOP w0.081: v1(5.13,7.16) U1.F22
RGMII1_RD0: length 0.7
  TOP w0.081: v1(7.7,15.17) U1.AB17
RGMII1_RD1: length 2.1
  TOP w0.081: U1.AC17 8.41,15.41 8.41,17.16
RGMII1_RD2: length 0.5
  TOP w0.081: v1(8.65,15.11) U1.AB16
RGMII1_RD3: length 0.5
  TOP w0.081: v1(8.68,14.2) U1.AA15
RGMII1_RXC: length 1.6
  TOP w0.081: U1.AD17 7.91,15.91 7.91,17.16
RGMII1_TD1: length 1.6
  TOP w0.081: 6.41,17.16 6.41,15.91 U1.AD20
RGMII1_TD3: length 1.6
  TOP w0.081: U1.AD18 7.41,15.91 7.41,17.16
RGMII1_TX_CTL: length 1.6
  TOP w0.081: U1.AD19 6.91,15.91 6.91,17.16
RGMII2_RD1: length 0.4
  TOP w0.081: U1.AB20 6.78,14.65 v1(7.1,14.65)
RGMII2_RD2: length 0.5
  TOP w0.081: v1(5.69,15.18) U1.AC21
RGMII2_RX_CTL: length 1.6
  TOP w0.081: U1.AD22 5.41,15.91 5.41,17.16
RGMII2_RXC: length 1.6
  TOP w0.081: U1.AD23 4.91,15.91 4.91,17.16
RGMII2_TD0: length 0.7
  TOP w0.081: U1.Y18 v1(8.13,14.17)
RGMII2_TD1: length 0.5
  TOP w0.081: v1(7.66,14.61) U1.AA18
RGMII2_TD2: length 1.6
  TOP w0.081: U1.AD21 5.91,15.91 5.91,17.16
RGMII2_TD3: length 0.5
  TOP w0.081: U1.AC20 v1(7.11,15.21)
RGMII2_TX_CTL: length 0.5
  TOP w0.081: v1(6.66,14.16) U1.AA19
SPI0_CS1: length 0.5
  TOP w0.081: U1.C13 v1(10.69,5.16)
SPI0_D0: length 1.6
  TOP w0.081: 9.91,3.16 9.91,4.41 U1.B13
SPI0_D1: length 1.6
  TOP w0.081: 9.41,3.16 9.41,4.41 U1.B14
TCK: length 2.1
  TOP w0.081: U1.C11 11.41,4.91 11.41,3.16
TDO: length 0.5
  TOP w0.081: v1(10.16,5.63) U1.D12
TEMP_DIODE_P: length 0.5
  TOP w0.081: U1.E7 v1(13.67,6.16)
TMS: length 1.6
  TOP w0.081: 10.91,3.16 10.91,4.41 U1.B11
TRSTN: length 1.6
  TOP w0.081: 11.91,3.16 11.91,4.41 U1.B10
UART0_RTSN: length 1.6
  TOP w0.081: U1.B15 8.91,4.41 8.91,3.16
UART0_RXD: length 0.5
  TOP w0.081: v1(9.64,5.14) U1.D14
UART0_TXD: length 0.7
  TOP w0.081: v1(9.17,5.65) U1.E14
USB0_DP: length 1.6
  TOP w0.081: 11.41,17.16 11.41,15.91 U1.AD11
USB0_DRVVBUS: length 0.4
  TOP w0.081: U1.C20 v1(7.1,5.13)
USB0_RCALIB: length 1.6
  TOP w0.081: U1.AD10 11.91,15.91 11.91,17.16
USB0_VBUS: length 2.1
  TOP w0.081: U1.AC11 10.91,15.41 10.91,17.16
USB1_DM: length 1.6
  TOP w0.081: 12.41,17.16 12.41,15.91 U1.AD9
USB1_DRVVBUS: length 0.5
  TOP w0.081: v1(7.13,6.66) U1.F18
USB1_ID: length 0.5
  TOP w0.081: v1(11.67,15.16) U1.AC9
USB1_RCALIB: length 0.7
  TOP w0.081: U1.AB9 v1(12.63,15.18)
VMON_1P8_SOC: length 0.4
  TOP w0.081: v1(11.62,6.72) U1.G10
VMON_3P3_SOC: length 0.5
  TOP w0.081: v1(11.63,9.13) 11.64,8.78 U1.K10
VMON_VSYS: length 0.4
  TOP w0.081: v1(11.64,8.1) U1.H10
VOUT0_DATA0: length 0.4
  TOP w0.081: U1.U22 v1(5.69,12.61)
VOUT0_DATA1: length 1.6
  TOP w0.081: 3.16,12.91 4.41,12.91 U1.V24
VOUT0_DATA3: length 1.6
  TOP w0.081: 3.16,13.41 4.41,13.41 U1.W24
VOUT0_DATA5: length 1.6
  TOP w0.081: 3.16,13.91 4.41,13.91 U1.Y24
VOUT0_DATA6: length 0.5
  TOP w0.081: v1(5.15,13.2) U1.Y23
VOUT0_DATA8: length 0.7
  TOP w0.081: U1.V21 v1(6.65,13.16)
VOUT0_DATA9: length 0.5
  TOP w0.081: v1(5.71,13.17) U1.W21
VOUT0_DATA10: length 0.5
  TOP w0.081: U1.V20 v1(7.17,12.66)
VOUT0_DATA11: length 0.5
  TOP w0.081: v1(5.12,14.64) U1.AA23
VOUT0_DATA13: length 1.6
  TOP w0.081: U1.AA24 4.41,14.41 3.16,14.41
VOUT0_DATA14: length 0.5
  TOP w0.081: U1.Y22 v1(5.68,14.15)
VOUT0_DATA15: length 1.6
  TOP w0.081: U1.AB24 4.41,14.91 3.16,14.91
VOUT0_DE: length 0.5
  TOP w0.081: v1(6.14,14.65) U1.AA21
VOUT0_PCLK: length 0.5
  TOP w0.081: v1(6.16,13.65) U1.Y20
VOUT0_VSYNC: length 1.6
  TOP w0.081: U1.AC24 4.41,15.41 3.16,15.41
VPP: length 0.5
  TOP w0.081: v1(12.66,8.64) U1.J8
WKUP_I2C0_SCL: length 1.6
  TOP w0.081: U1.B9 12.41,4.41 12.41,3.16
WKUP_UART0_CTSN: length 0.4
  TOP w0.081: v1(13.22,5.12) U1.C6
WKUP_UART0_RXD: length 1.6
  TOP w0.081: 14.91,3.16 14.91,4.41 U1.B4
WKUP_UART0_TXD: length 0.5
  TOP w0.081: U1.C5 v1(14.65,5.16)

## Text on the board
BOTTOM: VDD_CORE | CAP_VDDSHV_MMC1 | CAP* | (VDDA_PLL 0,1,2) | PLL SUPP | IO SUPPLIES | VDDA*, VDDSHV
